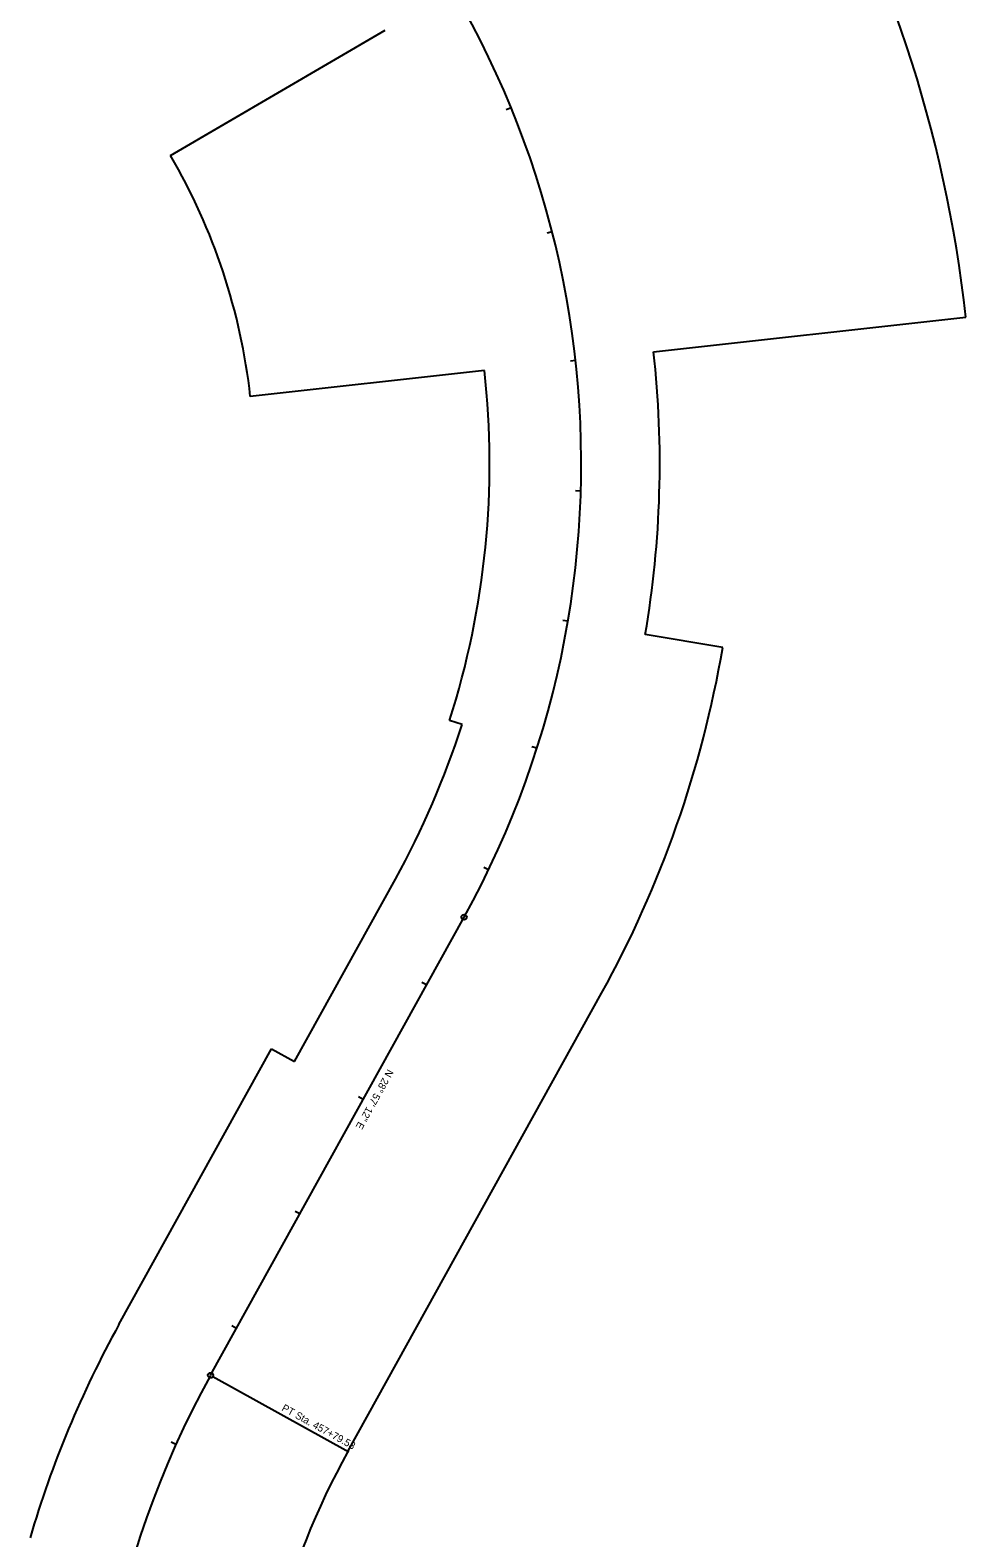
# Model space of a CAD drawing. Extents: x 2353716 to 2355698, y 707997 to 710626.
# Drawn here: x 2355157 to 2355515, y 708789 to 709365 of the extents above; entities that cross this region are included whole.
import ezdxf

# ---------------------------------------------------------------- set-up
doc = ezdxf.new("R2010")
doc.units = 0
doc.layers.add('RW_X_CL_20', color=7, linetype='Continuous')
doc.layers.add('RW_X_Fee_RW', color=7, linetype='Continuous')

msp = doc.modelspace()

# ---------------------------------------------------------------- linework, layer by layer
at = {"layer": 'RW_X_CL_20'}
for p, q in [((2355341.18, 709334.97), (2355339.33, 709334.21)), ((2355356.88, 709287.54), (2355354.94, 709287.05)), ((2355365.82, 709238.39), (2355363.84, 709238.17)), ((2355367.84, 709188.47), (2355365.84, 709188.53)), ((2355362.89, 709138.76), (2355360.92, 709139.09)), ((2355351.07, 709090.22), (2355349.16, 709090.82)), ((2355332.6, 709043.79), (2355330.8, 709044.66)), ((2355226.39, 708850.61), (2355323.24, 709025.66)), ((2355226.39, 708850.61), (2355323.24, 709025.66)), ((2355308.91, 708999.77), (2355307.16, 709000.74)), ((2355284.71, 708956.02), (2355282.96, 708956.99)), ((2355260.5, 708912.27), (2355258.75, 708913.24)), ((2355236.3, 708868.52), (2355234.55, 708869.49)), ((2355227.26, 708850.12), (2355279.19, 708821.39)), ((2355213.17, 708824.21), (2355211.35, 708825.03))]:
    msp.add_line(p, q, dxfattribs=at)
for centre in [(2355323.24, 709025.66), (2355226.39, 708850.61)]:
    msp.add_circle(centre, 1, dxfattribs=at)
for centre, start, end in [((2355009.9, 709199.02), 331.04655, 42.71322), ((2355539.73, 708677.25), 151.04655, 225.87988), ((2355539.73, 708677.25), 151.04655, 225.87988)]:
    msp.add_arc(centre, 358.1, start, end, dxfattribs=at)
at = {"layer": 'RW_X_Fee_RW'}
for p, q in [((2355211.13, 709316.67), (2355293.14, 709364.61)), ((2355395.64, 709241.69), (2355514.92, 709254.88)), ((2355331.04, 709234.54), (2355241.58, 709224.65)), ((2355422.03, 709128.66), (2355392.46, 709133.71)), ((2355322.48, 709099.33), (2355317.72, 709100.85)), ((2355258.46, 708970.54), (2355296.99, 709040.19)), ((2355278.89, 708821.56), (2355375.74, 708996.62)), ((2355191.39, 708869.97), (2355249.71, 708975.38)), ((2355249.71, 708975.38), (2355258.46, 708970.54))]:
    msp.add_line(p, q, dxfattribs=at)
for centre, radius, start, end in [((2355009.9, 709199.02), 508.1, 6.31199, 30.3119), ((2355009.9, 709199.02), 233.1, 6.31199, 30.3119), ((2355009.9, 709199.02), 388.1, 350.31205, 6.31199), ((2355009.9, 709199.02), 323.1, 342.31208, 6.31199), ((2355009.9, 709199.02), 418.1, 331.04655, 350.31205), ((2355009.9, 709199.02), 328.1, 331.04655, 342.31208), ((2355539.73, 708677.25), 398.1, 151.04655, 163.77132), ((2355539.73, 708677.25), 298.1, 151.04655, 179.77126)]:
    msp.add_arc(centre, radius, start, end, dxfattribs=at)

# ---------------------------------------------------------------- texts
at = {"layer": 'RW_X_CL_20'}
for s, rotation, p in [('N 28%%d 57\' 12" E', 241.04655, (2355294.02, 708967.8)), ('PT Sta. 457+79.53', 331.04655, (2355253.32, 708837.31))]:
    msp.add_text(s, height=2.8, rotation=rotation, dxfattribs=at).set_placement(p)

doc.saveas('drawing.dxf')
